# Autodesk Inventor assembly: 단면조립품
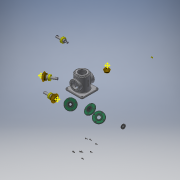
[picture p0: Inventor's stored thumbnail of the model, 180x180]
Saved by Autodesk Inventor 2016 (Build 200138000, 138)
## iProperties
Created: 2019-08
Part Number: 단면조립품
Material: 일반
Document SubType Name: Assembly
Designer: user
Author: user
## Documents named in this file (16)
- D:\490823V1003\단면조립품.iam
- D:\490823V1003\메인 베벨기어.ipt
- D:\490823V1003\메인 축.ipt
- 메인 축.ipt
- D:\490823V1003\베어링 6203.ipt
- D:\490823V1003\본체.ipt
- D:\490823V1003\볼트 M4.ipt
- 볼트 M4.ipt
- D:\490823V1003\서브 베벨기어.ipt
- D:\490823V1003\서브 축.ipt
- 서브 축.ipt
- D:\490823V1003\오일 실.ipt
- 오일 실.ipt
- D:\490823V1003\커버.ipt
- D:\490823V1003\키 4x4.ipt
- D:\490823V1003\키 5x5.ipt
